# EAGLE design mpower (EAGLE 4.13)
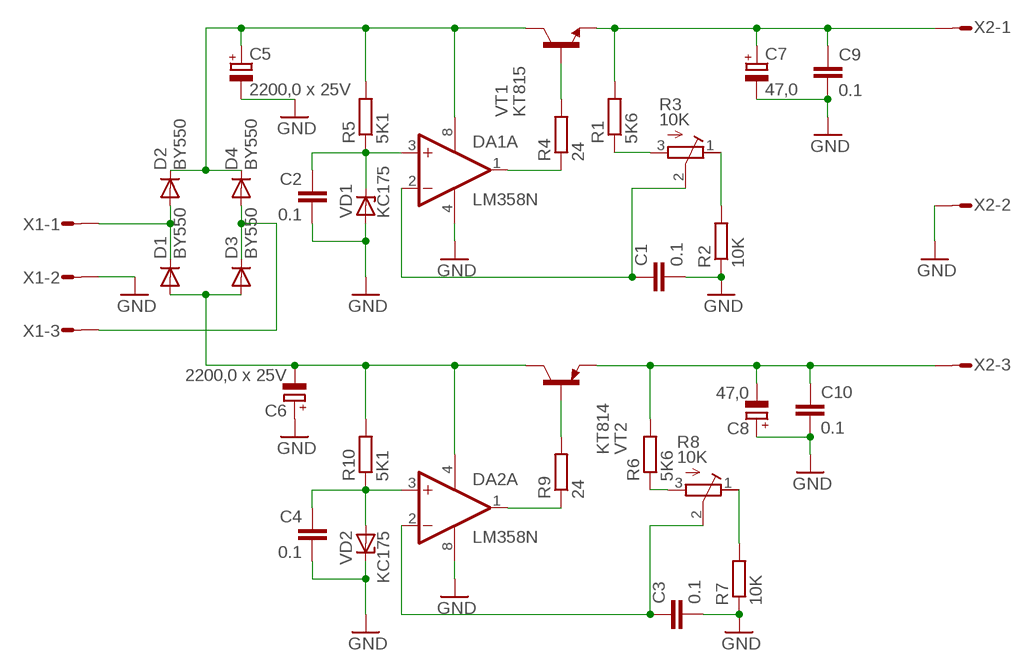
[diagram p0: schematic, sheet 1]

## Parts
C1  0.1  C-EU025-025X050  [C025-025X050]
C2  0.1  C-EU025-025X050  [C025-025X050]
C3  0.1  C-EU025-025X050  [C025-025X050]
C4  0.1  C-EU025-025X050  [C025-025X050]
C5  2200,0 x 25V  CPOL-EUE5-10.5  [E5-10,5]
C6  2200,0 x 25V  CPOL-EUE5-10.5  [E5-10,5]
C7  47,0  CPOL-EUE2.5-6  [E2,5-6]
C8  47,0  CPOL-EUE2.5-6  [E2,5-6]
C9  0.1  C-EU025-025X050  [C025-025X050]
C10  0.1  C-EU025-025X050  [C025-025X050]
D1  BY550  [DO27-15]
D2  BY550  [DO27-15]
D3  BY550  [DO27-15]
D4  BY550  [DO27-15]
DA1  LM358N  [DIL08]
DA2  LM358N  [DIL08]
R1  5K6  R-EU_0207/12  [0207/12]
R2  10K  R-EU_0207/12  [0207/12]
R3  10K  R-TRIMMT93XB  [RTRIMT93XB]
R4  24  R-EU_0207/12  [0207/12]
R5  5K1  R-EU_0207/12  [0207/12]
R6  5K6  R-EU_0207/12  [0207/12]
R7  10K  R-EU_0207/12  [0207/12]
R8  10K  R-TRIMMT93XB  [RTRIMT93XB]
R9  24  R-EU_0207/12  [0207/12]
R10  5K1  R-EU_0207/12  [0207/12]
VD1  KC175  1N4728  [DO41Z10]
VD2  KC175  1N4728  [DO41Z10]
VT1  KT815  -NPN-TO225AA  [TO225AA]
VT2  KT814  -PNP-TO225AA  [TO225AA]
X1  MT6-3  [MT6-3]
X2  MT6-3  [MT6-3]

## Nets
GND: C1.2 C2.2 C3.2 C4.2 C5.- C6.+ C7.- C8.+ C9.2 C10.2 DA1.4(P:V-) DA2.8(P:V+) R2.1 R7.1 VD1.A VD2.C X1.2 X2.2
N$1: DA1.1(A:OUT) R4.1
N$2: C5.+ D2.C D4.C DA1.8(P:V+) R5.2 VT1.2(C)
N$3: C7.+ C9.1 R1.2 VT1.3(E) X2.1
N$4: R1.1 R3.3(E)
N$5: R2.2 R3.1(A)
N$6: C1.1 DA1.2(A:-IN) R3.2(S)
N$7: C2.1 DA1.3(A:+IN) R5.1 VD1.C
N$8: R4.2 VT1.1(B)
N$10: C8.- C10.1 R6.2 VT2.3(E) X2.3
N$11: R6.1 R8.3(E)
N$12: R7.2 R8.1(A)
N$13: DA2.1(A:OUT) R9.1
N$14: C3.1 DA2.2(A:-IN) R8.2(S)
N$15: R9.2 VT2.1(B)
N$16: C4.1 DA2.3(A:+IN) R10.1 VD2.A
N$17: D1.C D2.A X1.1
N$18: D3.C D4.A X1.3
N$19: C6.- D1.A D3.A DA2.4(P:V-) R10.2 VT2.2(C)
Unconnected: DA1.5(B:+IN) DA1.6(B:-IN) DA1.7(B:OUT) DA2.5(B:+IN) DA2.6(B:-IN) DA2.7(B:OUT)

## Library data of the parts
C1-C4 C9 C10 = rcl:C-EU: CAPACITOR, European symbol
C5-C8 = rcl:CPOL-EU: POLARIZED CAPACITOR, European symbol
D1-D4 = diode:BY550: DIODE
DA1 DA2 = linear:LM358: OP AMP
R1 R2 R4-R7 R9 R10 = rcl:R-EU_: RESISTOR, European symbol
R3 R8 = rcl:R-TRIMM: Trimm resistor
VD1 VD2 = diode:1N4728: Z DIODE
VT1 = transistor:*-NPN-: NPN Transistror
VT2 = transistor:*-PNP-: PNP Transistror
X1 X2 = con-amp-mt:MT6-3: AMP MT6 CONNECTOR

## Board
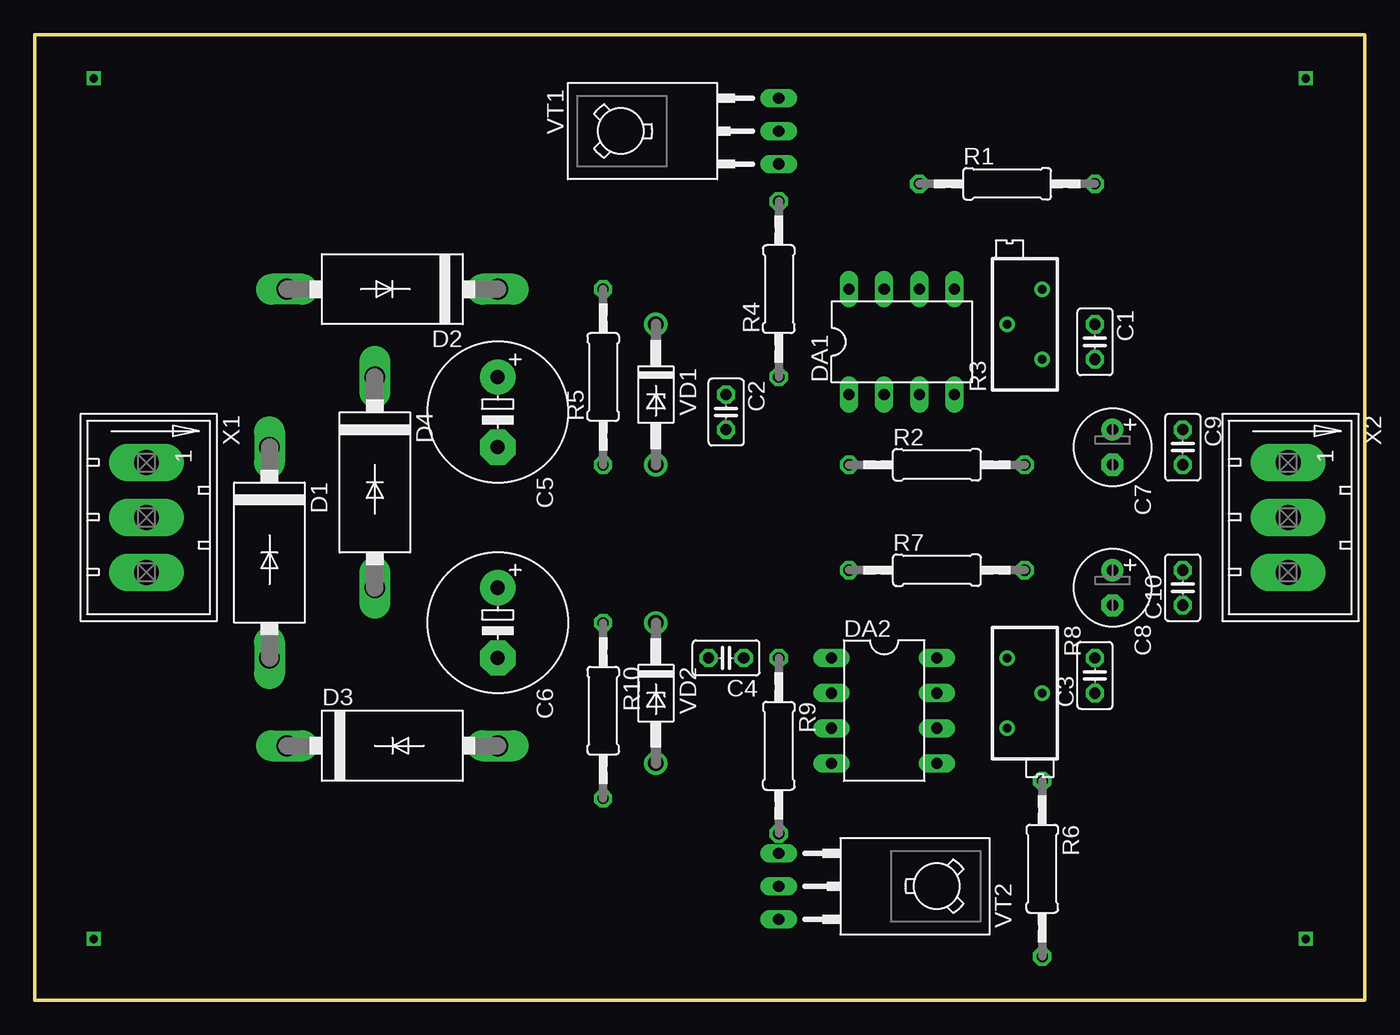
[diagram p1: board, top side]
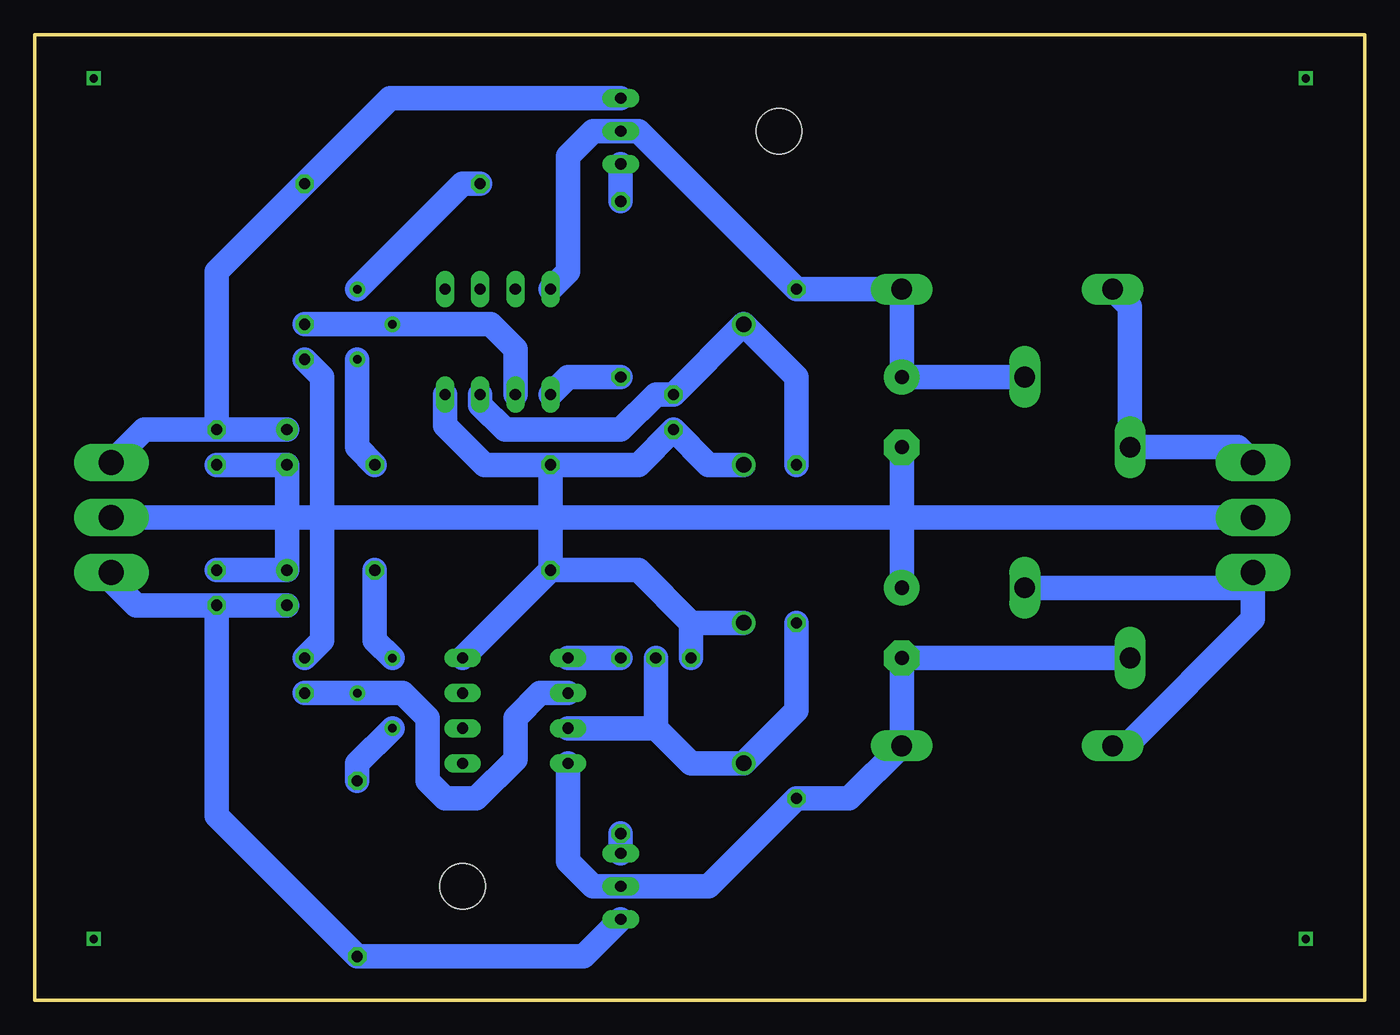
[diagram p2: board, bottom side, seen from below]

Size 96.19 x 69.84 mm. Coordinates in mm from the lower left corner, seen from the top.
Outline: 0,0 96.19,0 96.19,69.84 0,69.84 0,0
Copper layers (1*16): Top 0.035mm / dielectric 1.5mm / Bottom 0.035mm
Design rules "default": minimum track width 10mil, minimum drill 24mil, track to track 8mil, track to pad 8mil, pad to pad 8mil, via to via 8mil, smd to smd 8mil, copper to edge 40mil, drill to drill 8mil, minimum pad ring 10mil, minimum via ring 8mil, stop-mask expansion 4mil, vias tented up to drill 0mil, thermal gap 10mil

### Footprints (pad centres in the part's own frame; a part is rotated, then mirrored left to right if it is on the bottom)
C025-025X050 = drill 0.813 octagon: 1 -1.27,0; 2 1.27,0
E5-10,5 = drill 1.016 pad 2.54 round: + -2.54,0 | drill 1.016 pad 2.54 octagon: - 2.54,0
E2,5-6 = drill 0.813 pad 1.6 round: + -1.27,0 | drill 0.813 pad 1.6 octagon: - 1.27,0
DO27-15 = drill 1.499 long: A 7.62,0; C -7.62,0
DIL08 = drill 0.813 long: 1 -3.81,-3.81; 2 -1.27,-3.81; 3 1.27,-3.81; 4 3.81,-3.81; 5 3.81,3.81; 6 1.27,3.81; 7 -1.27,3.81; 8 -3.81,3.81
0207/12 = drill 0.813 octagon: 1 -6.35,0; 2 6.35,0
RTRIMT93XB = drill 0.61 round: 1 1.27,-2.54; 2 -1.27,0; 3 1.27,2.54
DO41Z10 = drill 1.118 round: A 5.08,0; C -5.08,0
TO225AA = drill 0.813 long: 1 -2.381,-11.43; 2 0,-11.43; 3 2.381,-11.43 | hole 3.302: 0,0
MT6-3 = drill 1.803 long: 1 -3.962,0; 2 0,0; 3 3.962,0

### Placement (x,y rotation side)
C1  76.67,47.62 270 top
C2  50,42.54 270 top
C3  76.67,23.49 90 top
C4  50,24.76 180 top
C5  33.49,42.54 270 top
C6  33.49,27.3 270 top
C7  77.94,40 270 top
C8  77.94,29.84 270 top
C9  83.02,40 270 top
C10  83.02,29.84 90 top
D1  16.98,32.38 270 top
D2  25.87,51.43 180 top
D3  25.87,18.41 0 top
D4  24.6,37.46 270 top
DA1  62.7,47.62 0 top
DA2  61.43,20.95 270 top
R1  70.32,59.05 0 top
R2  65.24,38.73 0 top
R3  71.59,48.89 0 top
R4  53.81,51.43 90 top
R5  41.11,45.08 90 top
R6  72.86,9.52 270 top
R7  65.24,31.11 0 top
R8  71.59,22.22 180 top
R9  53.81,18.41 270 top
R10  41.11,20.95 270 top
VD1  44.92,43.81 270 top
VD2  44.92,22.22 270 top
VT1  42.38,62.86 90 top
VT2  65.24,8.25 270 top
X1  8.09,34.92 270 top
X2  90.64,34.92 270 top

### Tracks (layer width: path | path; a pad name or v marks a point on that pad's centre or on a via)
GND
  Bottom 1.778: 33.49,34.92 C6.+ | 33.49,34.92 C5.- | X1.2 33.49,34.92 | 33.49,34.92 58.89,34.92 | 58.89,34.92 75.4,34.92 | 75.4,34.92 77.94,34.92 | 77.94,34.92 X2.2 | VD1.A 47.46,38.73 C2.2 52.54,38.73 R2.1 | R2.1 63.67,38.73 66.51,41.57 DA1.4 | 75.4,34.92 75.4,45.08 C1.2 | 58.89,34.92 R2.1 | 77.94,34.92 C7.- C9.2 | 48.73,27.3 VD2.C | 48.73,27.3 C4.2 | R7.1 DA2.8 | 58.89,34.92 R7.1 | R7.1 52.54,31.11 48.73,27.3 | 75.4,34.92 75.4,26.03 C3.2 | C10.2 C8.+ 77.94,34.92
N$1
  Bottom 1.778: R4.1 57.62,45.08 DA1.1
N$2
  Bottom 1.778: DA1.8 57.62,52.7 57.62,61.06 55.82,62.86 VT1.2 52.54,62.86 R5.2 D2.C C5.+ D4.C
N$3
  Bottom 1.778: C7.+ C9.1 | X2.1 88.25,41.27 C9.1 | C9.1 83.02,52.7 R1.2 70.48,65.24 VT1.3
N$4
  Bottom 1.778: R1.1 65.24,59.05 R3.3
N$5
  Bottom 1.778: R2.2 72.86,40 R3.1
N$6
  Bottom 1.778: DA1.2 61.43,47.09 63.23,48.89 R3.2 C1.1
N$7
  Bottom 1.778: R5.1 41.11,45.08 VD1.C C2.1 51.27,43.81 53.81,41.27 62.17,41.27 63.97,43.07 DA1.3
N$8
  Bottom 1.778: VT1.1 R4.2
N$9  (via drill 0.6)
  other vias: 4.28,66.67
N$10
  Bottom 1.778: X2.3 90.64,30.37 88.84,28.57 C10.1 | C10.1 C8.- C10.1 | C10.1 83.02,13.33 R6.2 56.51,3.17 VT2.3
N$11
  Bottom 1.778: R8.3 72.86,17.14 R6.1
N$12
  Bottom 1.778: R8.1 71.59,26.03 R7.2
N$13
  Bottom 1.778: DA2.1 R9.1
N$14
  Bottom 1.778: DA2.2 59.63,22.22 61.43,20.42 61.43,17.44 64.27,14.6 66.51,14.6 67.78,15.87 67.78,20.42 69.58,22.22 R8.2 C3.1
N$15
  Bottom 1.778: VT2.1 R9.2
N$16
  Bottom 1.778: R10.1 41.11,20.95 VD2.A 48.73,17.14 51.27,19.68 | 51.27,19.68 C4.1 | 51.27,19.68 DA2.3
N$17
  Bottom 1.778: D2.A 16.98,50.16 D1.C 9.21,40 X1.1 8.09,38.73
N$18
  Bottom 1.778: 8.09,31.11 X1.3 8.09,29.84 | D3.C 17.25,18.41 8.09,27.57 8.09,29.84 | 8.09,29.84 D4.A
N$19
  Bottom 1.778: DA2.4 57.62,10.05 55.82,8.25 VT2.2 47.46,8.25 R10.2 37.3,14.6 D3.A C6.- D1.A
N$20  (via drill 0.6)
  other vias: 91.91,66.67
N$21  (via drill 0.6)
  other vias: 91.91,4.44
N$22  (via drill 0.6)
  other vias: 4.28,4.44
